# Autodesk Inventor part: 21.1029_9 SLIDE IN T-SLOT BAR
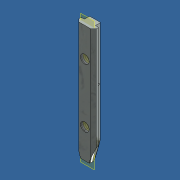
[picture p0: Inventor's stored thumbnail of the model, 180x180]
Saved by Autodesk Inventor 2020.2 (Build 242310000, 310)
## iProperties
Created: 2006-12
Part Number: 21.1029_9 SLIDE IN T-SLOT BAR
Material: Steel
Document SubType Name: Modeling
Designer: Andy Moles
Mass: 54.3517 g
Surface Area: 38.9719 cm^2
Volume: 6.92378 cm^3
Density: 7.85 g/cm^3
Description: T-Slot Bar 90 Body
Appearance: Zinc
Author: Andy Moles
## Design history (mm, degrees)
sketch "Sketch1"
  geometry: L1 (-4.25, 0)-(-4.25, 3.5) reference; L2 (-6.2, 0)-(-4.25, 0) reference; L3 (-6.7, -0.5)-(-6.2, 0) reference; L4 (-6.7, -2)-(-6.7, -0.5) reference; L5 (-4.7, -4)-(-6.7, -2) reference; L6 (4.7, -4)-(-4.7, -4) reference; L7 (6.7, -2)-(4.7, -4) reference; L8 (6.7, -0.5)-(6.7, -2) reference; L9 (6.2, 0)-(6.7, -0.5) reference; L10 (4.25, 0)-(6.2, 0) reference; L11 (4.25, 3.5)-(4.25, 0) reference; L12 (3.75, 4)-(4.25, 3.5) reference; L13 (-3.75, 4)-(3.75, 4) reference; L14 (-4.25, 3.5)-(-3.75, 4) reference; 2 further points
  constraints: 28 end point, 4 horizontal, 4 vertical, 22 other
extrude "Extrusion1" new body sketch "Sketch1" stored distance "d0" = 90; taper "d1" = 0 deg
sketch "Sketch2"
  geometry: L1 (0, -90)-(7.5, -90) reference; L2 (0, 0)-(0, -90) reference; 4 further points; 1 other entity
  constraints: 1 vertical alignment, 1 other
  dimensions: "d2" = 7.5 distance of point (7.5, 0) L2.start (derived); "d3" = 3.75 distance from line of point (3.75, -22.5) L2 (= 0.5 x d2); "d4" = 22.5 dimension on point (3.75, -22.5); "d5" = 22.5 distance from line of point (3.75, -67.5) L1
hole "Hole1" sketch "Sketch2" at (3.75, -22.5), (3.75, -67.5) diameter "d6" = 6.647; stored, may be unused: countersink angle "d10" = 90 deg, drill point angle "d12" = 118 deg; dims "d7" = 6, "d8" = 4, "d9" = 2, "d11" = 8
sketch "Sketch3"
  geometry: L1 (-4.25, 0)-(-4.05, 0); L2 (-4.05, 0)-(-4.05, 5.225); L3 (-4.05, 5.225)-(-4.25, 5.225); L4 (-4.25, 5.225)-(-4.25, 0); L5 (4.25, 0)-(4.05, 0); L6 (4.05, 0)-(4.05, 8.594); L7 (4.05, 8.594)-(4.25, 8.594); L8 (4.25, 8.594)-(4.25, 0); 1 further point
  constraints: 16 end point, 5 parallel, 2 horizontal, 2 perpendicular
  dimensions: "d13" = 8.1 distance between parallel lines of L6 L2
extrude "Extrusion2" cut sketch "Sketch3" distance "d14" = 50; taper "d15" = 0 deg
workplane "Work Plane3"
sketch "Sketch7"
  geometry: L1 (11.4, -90)-(11.4, 0) reference; L2 (-2, -90)-(-2, 0) reference; L3 (8.45, -90)-(0.95, -90) reference; L4 (4.7, -90)-(4.7, -70); L5 (8.54, -90)-(13.899, -70); L6 (13.899, -70)-(13.899, -90); L7 (13.899, -90)-(8.54, -90); 1 further point
  constraints: 8 end point, 1 horizontal, 1 horizontal alignment, 1 midpoint, 1 perpendicular, 1 point on line, 1 vertical
  dimensions: "d22" = 20 distance of L4.start L4.end; "d23" = 15 deg angle of L5 L1
revolve "Revolution1" sketch "Sketch7" stored, may be unused: angle "d24" = 90 deg
fillet "Fillet1" dims "d25" = 3.175
body "Solid1"
other parameters: "d21" = -2
